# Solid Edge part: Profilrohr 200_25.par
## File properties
Username: ahadarics
Dokumentum tartalom típus: 0
Author: ahadarics
Last saved by: ahadarics
Revision: 78
Sűrűség: 0,000 kg/m^3
Pontosság: 0,990
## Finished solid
Body 1: solid body, 6 faces, 9 edges, 5 vertices.
  Faces by surface: cone 2, cylinder 2, plane 2
  Edges by curve: circle 6, line 3
Bounding box of the edges (mm): 210.000 x 105.000 x 210.000, from (-105, -52.5, -105) to (105, 52.5, 105).
Cylindrical faces by radius (mm): R100 x1, R105 x1
Conical faces (half-angle, radius in mm at the cone's reference point): 45 deg R100.25 x2
Planar faces by outward normal: +y 1, -y 1
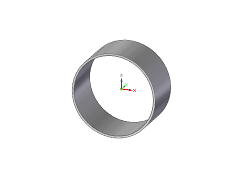
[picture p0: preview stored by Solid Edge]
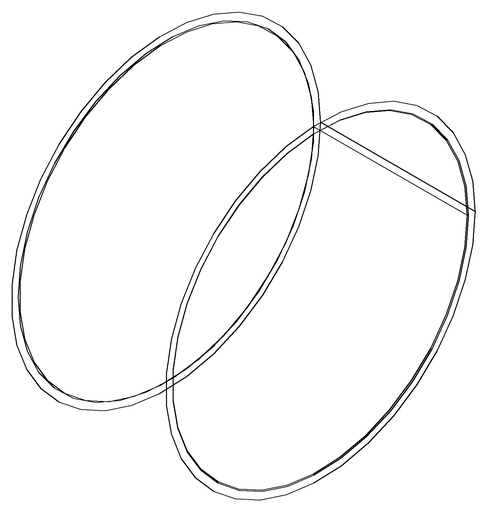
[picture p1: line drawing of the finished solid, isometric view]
